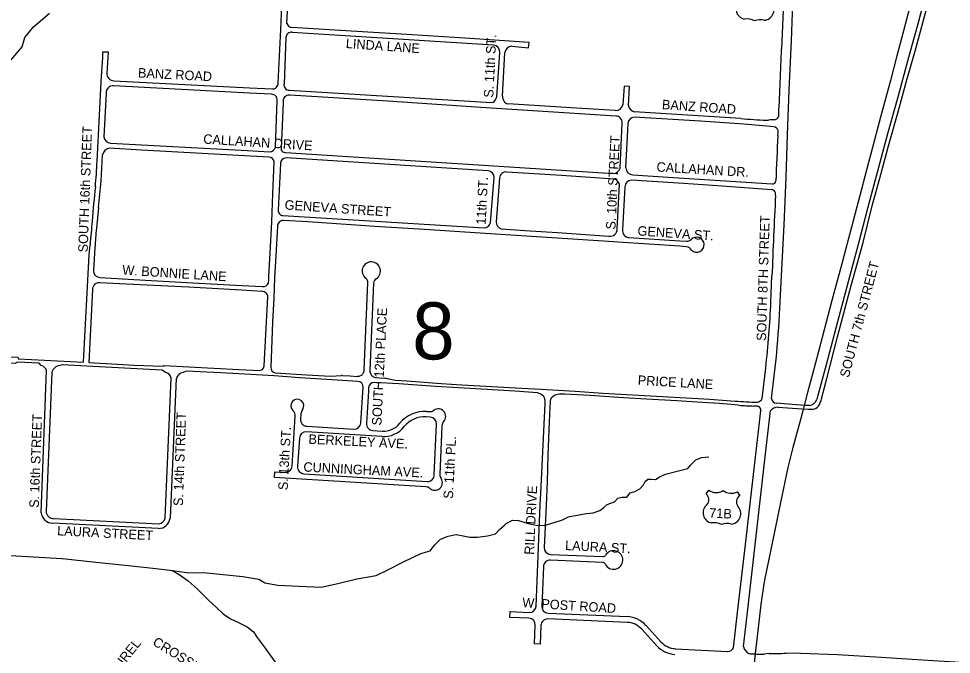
# Model space of a CAD drawing. Extents: x 0 to 712119, y 0 to 761125.
# Drawn here: x 681680 to 686589, y 720273 to 723620 of the extents above; entities that cross this region are included whole.
import ezdxf

# ---------------------------------------------------------------- set-up
doc = ezdxf.new("R2010")
doc.units = 0
for name, color, linetype in [('Arkansas-Missouri Railroad', 7, 'Continuous'), ('HWY signs', 7, 'Continuous'), ('PAVED ROADS', 7, 'Continuous'), ('Priority 8', 7, 'Continuous'), ('stream or creek', 7, 'Continuous'), ('street names', 7, 'Continuous')]:
    doc.layers.add(name, color=color, linetype=linetype)

msp = doc.modelspace()

# ---------------------------------------------------------------- linework, layer by layer
at = {"layer": 'Arkansas-Missouri Railroad'}
msp.add_lwpolyline([(686370.6, 723681.9), (686319.3, 723488.6), (686319.3, 723488.6), (686302.3, 723424.6), (686268, 723295.2), (686268, 723295.2), (686216.7, 723101.9), (686216.7, 723101.9), (686165.4, 722908.6), (686165.4, 722908.6), (686153.3, 722863.2), (686114.1, 722715.3), (686114.1, 722715.3), (686062.8, 722522), (686062.8, 722522), (686031.1, 722402.2), (686011.5, 722328.6), (686011.5, 722328.6), (685960.3, 722135.3), (685960.3, 722135.3), (685909, 721942), (685909, 721942), (685889.3, 721868), (685857.7, 721748.7), (685857.7, 721748.7), (685832, 721652), (685806.4, 721555.4), (685806.4, 721555.4), (685795.7, 721515), (685755.2, 721362), (685755.2, 721362), (685727.4, 721256.8), (685688, 721063.9), (685688, 721063.9), (685647.8, 720867.9), (685647.8, 720867.9), (685607.7, 720672), (685607.7, 720672), (685602, 720644.3), (685586.6, 720535.3), (685579.5, 720474.1), (685579.5, 720474.1), (685556.6, 720275.4), (685556.6, 720275.4), (685548.8, 720206.9)], dxfattribs=at)
at = {"layer": 'HWY signs'}
for points in [[(685297.6, 721119), (685312.7, 721137.4)], [(685387.6, 721135.4), (685387.6, 721135.4)], [(685462.3, 721129.6), (685475.4, 721109.7)]]:
    msp.add_lwpolyline(points, dxfattribs=at)
for centre, radius, start, end in [((685510.2, 723670.5), 54.5, 128.6765, 259.9158), ((685600.3, 723665.8), 54.5, 274.1051, 45.3444), ((685515, 723544.6), 73.6, 59.7374, 101.2498), ((685582.4, 723541.1), 73.6, 72.7711, 114.2835), ((685270.4, 721087.6), 41.5, 320.1078, 49.1208), ((685351.6, 721193.6), 68.4, 235.2382, 301.7199), ((685429.4, 721189.5), 68.4, 232.3011, 298.7827), ((685499.1, 721075.7), 41.5, 124.9002, 213.9131), ((685336.3, 721018.5), 54.5, 128.6765, 259.9158), ((685426.4, 721013.8), 54.5, 274.1051, 45.3444), ((685341.1, 720892.7), 73.6, 59.7374, 101.2498), ((685408.5, 720889.2), 73.6, 72.7711, 114.2835)]:
    msp.add_arc(centre, radius, start, end, dxfattribs=at)
at = {"layer": 'PAVED ROADS'}
for points in [[(685686.5, 722095.5), (685694.5, 722266), (685708.6, 722534.3), (685718.9, 722785.6), (685727, 723009), (685735.5, 723244), (685747.5, 723503.1), (685756.8, 723750.9), (685772.3, 724116.8), (685794.1, 724626.3), (685823.1, 725340.7)], [(685773.5, 725345.2), (685749.1, 724736.5), (685723.3, 724121.6), (685714.1, 723905.9), (685705.6, 723704.9), (685695.2, 723460.5)], [(686568.2, 724178.4), (686538.2, 724067.4), (686472.6, 723821.8), (686415.4, 723605.3), (686358.1, 723397), (686306.8, 723206.9), (686253.5, 723013.3), (686205.1, 722836.5), (686147.8, 722620.8), (686099, 722431.5), (686045, 722234.5), (685989, 722024.5), (685930.5, 721797.5), (685881.5, 721616)], [(685906.1, 721617.8), (685933.5, 721725), (685990, 721945), (686062.2, 722214.7), (686124.1, 722441.4), (686172.4, 722634.7), (686217.1, 722799.7), (686257.7, 722950.5), (686308.5, 723128.9), (686355, 723297.3), (686399.7, 723455.8), (686464.9, 723696.2), (686522.3, 723922), (686560.3, 724062.8), (686578.7, 724124.4)], [(683092, 723593.7), (683097.8, 723723.7), (683103.6, 723862.7)], [(683045, 723281.5), (683059.5, 723562.2), (683062.6, 723647.7), (683064.5, 723701.6), (683067.2, 723781)], [(684275.5, 723474.6), (684364, 723467.1), (684366.5, 723494.4), (684028.2, 723516.5), (683694.5, 723537.7), (683429.1, 723554.4), (683117.7, 723573.7)], [(683086.5, 723520), (683076.5, 723277)], [(684178.7, 723480.2), (683118.6, 723547.9)], [(682093, 722869), (682105.5, 723111), (682114.5, 723289), (682122.3, 723416.3), (682122.7, 723446), (682150.8, 723445.3), (682149.8, 723414), (682144.5, 723333)], [(684198.9, 723233.3), (684212, 723442.4)], [(684225.9, 723212.4), (684239.2, 723442.2)], [(682180.5, 723293.5), (682895, 723256), (683016.5, 723250)], [(682139.5, 723227.5), (682128.6, 722998.3)], [(683010, 723222), (682895.5, 723228.5), (682178.8, 723266.4)], [(683104, 723243.5), (684167.9, 723177.9)], [(684890, 723160.9), (684895, 723263.1), (684866, 723264.5), (684859.9, 723166.9)], [(683031, 722943), (683040.5, 723190.5)], [(683071.5, 723179), (683060.5, 722938.5)], [(684823, 723106.5), (684113, 723151.7), (683623, 723185), (683106.5, 723217)], [(684820.9, 723136), (684644.2, 723146.9), (684253.6, 723172.1)], [(685481.4, 723093.7), (685285, 723106.1), (684919.3, 723129.8)], [(685654.5, 723050), (685636.5, 723052), (685496, 723064), (685268.5, 723080), (684920, 723101)], [(685634.8, 723086.8), (685626.6, 723085.4)], [(685656.4, 723086.6), (685649.3, 723086.8)], [(684844.9, 722832.9), (684856.1, 723071.7), (684856.1, 723071.7)], [(684885.5, 723065.7), (684874.5, 722833.9)], [(682996, 722891.5), (682326.5, 722927), (682156, 722937.5)], [(682163.5, 722964.7), (682883.8, 722926.1), (683000.5, 722919)], [(683084.5, 722915), (684810, 722804.9)], [(684151, 722819), (683087.5, 722886.5)], [(682994.5, 722230), (682996, 722242.5), (682997, 722264), (683003, 722385.5), (683011.5, 722550), (683018, 722697.5), (683019, 722738.5), (683024.5, 722866.5)], [(683057, 722858), (683045.5, 722612.5)], [(684163.4, 722545.7), (684181.8, 722782.9)], [(684211, 722779.7), (684193.1, 722549.5)], [(684813.6, 722774.8), (684536.4, 722793.6), (684249.6, 722812.5)], [(684911.6, 722798.4), (685097.5, 722785), (685645.4, 722750.2)], [(684830.5, 722512.5), (684841.5, 722746)], [(684870.4, 722735), (684858, 722508)], [(685643, 722719.5), (685383, 722738.5), (685178.5, 722752), (684904.5, 722768.9)], [(682099.5, 722625.5), (682089, 722517)], [(683070.5, 722583.5), (684129.6, 722518)], [(685194.5, 722419.5), (685159.6, 722421.9), (684888.5, 722439.3), (684784.5, 722446.1), (684514.4, 722464.4), (684324.7, 722476.9), (684109.5, 722490.2), (683815.8, 722509.5), (683555, 722525.9), (683201, 722550), (683073, 722558)], [(683042, 722526.5), (683033.6, 722370.7), (683027, 722254), (683022.5, 722149.5), (683016.5, 722022), (683007, 721785)], [(684218.7, 722512.8), (684344.7, 722504.7), (684516.3, 722493.3), (684786.5, 722475)], [(684890.4, 722468.2), (685160, 722450.5), (685194.5, 722448)], [(682020.4, 721811), (682051, 722377), (682055.5, 722430)], [(682081, 722414.5), (682073, 722293.5)], [(682108, 722257), (682286.5, 722246.5), (682565.5, 722231.5), (682854.5, 722215.5), (682963, 722209.5)], [(685639, 722130), (685644.7, 722264)], [(682068.5, 722194.5), (682049, 721809.4)], [(682961.5, 722183), (682853, 722190), (682573, 722205.5), (682319, 722219), (682105, 722230)], [(683498.5, 721770.4), (683518, 722228.3)], [(683547.9, 722227), (683528.4, 721767.2)], [(682972, 721792), (682991, 722155.5)], [(681798.5, 721793.5), (681787.5, 721805.5), (681674, 721811.5), (681660.5, 721804.5), (681509.5, 721812), (681399.5, 721817.5), (681298, 721822), (680643, 721852.5), (680562.5, 721856.5), (680505.5, 721857.5), (680412, 721859.5)], [(681486, 721846), (681675, 721837.5), (681679.5, 721829), (682020.4, 721811)], [(682049, 721809.4), (682287.5, 721796.5), (682438, 721790), (682443, 721793.5), (682839.2, 721773.7), (682949, 721768)], [(685643, 721619.5), (685666.5, 721826.5)], [(681797.5, 721019), (681826.5, 721767)], [(681854, 721756.5), (681824, 721026)], [(681909, 721797.5), (681896.5, 721794.5)], [(682452, 721757.5), (682435.5, 721769.5), (682069.5, 721789.5), (681909, 721797.5)], [(683464.2, 721710.4), (683464.2, 721710.6), (683330.4, 721719), (683157.7, 721729.8), (683024.5, 721739), (682744.5, 721755), (682560.5, 721764.5), (682545, 721757)], [(683030.5, 721756), (683196.5, 721745.5), (683320.5, 721737.5), (683378.1, 721741.4)], [(683492.8, 721751.7), (683492.4, 721751.9)], [(685593.5, 721621), (685612, 721782)], [(682450, 720992), (682481.5, 721727.5)], [(682509.5, 721725), (682477, 720990)], [(683384.1, 721741.9), (683425.1, 721739.2), (683461.4, 721736.9)], [(683480.6, 721741.3), (683480.8, 721740.8)], [(683532.9, 721748.5), (683532.5, 721748.3)], [(683543.4, 721736.4), (683543.7, 721736.8)], [(684402.8, 720527.3), (684425.4, 721059.8), (684428, 721120.1), (684450, 721593.5), (684451, 721604), (684451, 721611), (684449, 721617.5), (684446.5, 721623.5), (684443, 721630), (684435.5, 721638), (684424, 721645.5), (684410.5, 721650.5), (684290.4, 721658.7), (684115.3, 721669.8), (683873.4, 721683.8), (683681.5, 721697.5), (683552.1, 721705.3)], [(683561.2, 721730.7), (683580.9, 721729.5), (683606.8, 721728.1)], [(683611.3, 721727.4), (683661.5, 721716), (683661.5, 721716)], [(683661.5, 721716), (683723.5, 721712.5), (683904, 721700), (684011.5, 721693), (684138, 721685), (684294, 721676.5), (684430, 721668.5), (684608.5, 721659), (684754.5, 721649), (685068.5, 721630.5), (685317, 721617), (685451, 721607)], [(683481.1, 721491.7), (683492.7, 721678)], [(683521.7, 721676.7), (683520.6, 721658.7), (683510, 721489.9)], [(685469, 721584.5), (685368.5, 721593.5), (685276.4, 721599.5), (685143.6, 721608.1), (684983.9, 721617), (684863.7, 721624.4), (684688.6, 721635.6), (684554, 721642.5), (684526, 721643), (684515, 721641), (684504, 721637), (684495, 721632.5), (684488, 721628), (684483, 721622.5), (684479.5, 721616.5), (684477.5, 721610.5), (684476.5, 721605), (684472, 721500), (684464.5, 721321.5), (684460.6, 721181.9), (684455.4, 721058), (684445.9, 720835.7)], [(685442.3, 720307.9), (685464, 720494), (685508.5, 720881.5), (685552.6, 721265.5), (685579.2, 721493.8), (685586, 721557.5)], [(685495.5, 720314.5), (685519.5, 720526), (685604, 721267), (685636.5, 721556)], [(685566.5, 721580), (685550, 721580.5)], [(685584, 721568), (685580, 721573.5)], [(685841.5, 721583.5), (685821, 721583), (685750.5, 721589.5), (685667.5, 721595)], [(685677, 721575), (685801.5, 721565.5), (685836, 721563.5), (685862, 721564.5)], [(683118.8, 721263.9), (683135.4, 721527.5)], [(683165.2, 721539.9), (683163.4, 721511.6)], [(683845.7, 721521.9), (683824.7, 721523.3)], [(683826.7, 721552.2), (683841.2, 721551.3)], [(683196.6, 721473.9), (683443.4, 721458.5)], [(683867.4, 721217.7), (683878.8, 721484.9)], [(683907.4, 721476.6), (683896.5, 721220.6)], [(683157.2, 721411.8), (683147.8, 721262.1)], [(683591.6, 721420.1), (683194.8, 721445)], [(683543.2, 721452.2), (683593.4, 721449.1)], [(683823.5, 721155.1), (683026.7, 721205), (683028.5, 721234), (683081.2, 721230.7)], [(683181, 721224.4), (683829.7, 721183.8)], [(682415.5, 720935.5), (681859.5, 720963.5)], [(681865, 720989), (682417.5, 720961)], [(684751.9, 720757.6), (684478.1, 720769.3)], [(684479.4, 720799.3), (684753.2, 720787.6)], [(684441.7, 720735.8), (684432.7, 720526)], [(684265.7, 720468), (684267.1, 720498), (684366.3, 720493.8)], [(684466.2, 720489.5), (684883.4, 720471.8)], [(684365, 720463.8), (684265.7, 720468)], [(684428.5, 720426.1), (684424.2, 720326.3), (684394.3, 720327.9), (684398.5, 720427.4)], [(684882.1, 720441.8), (684464.9, 720459.6)], [(684981.1, 720426.1), (685060.1, 720339.1)], [(685037.9, 720318.9), (684958.9, 720405.9)], [(685135.6, 720303.2), (685411.5, 720288.5)], [(685630.5, 720278.5), (685604, 720274.5)], [(688147.5, 720143.5), (688112.5, 720143.5), (687799.5, 720160), (687514.5, 720180), (687351.5, 720185.5), (687076.5, 720202.7), (686756.3, 720223), (686492, 720240), (686219.5, 720257.5), (685990, 720270), (685795, 720277.5), (685717.5, 720279)]]:
    msp.add_lwpolyline(points, dxfattribs=at)
for centre, radius, start, end in [((683118.4, 723601.1), 27.5, 195.6597, 268.5413), ((683113.8, 723521), 27.4, 79.9384, 182.096), ((684176.1, 723444.4), 36, 356.9071, 85.807), ((684275.3, 723438.4), 36.3, 89.6802, 173.8729), ((660717.5, 724361.9), 24994, 357.14841, 357.93307), ((682180.2, 723329.4), 35.9, 174.2913, 270.4004), ((683016.1, 723279), 29, 270.8406, 4.8842), ((683103.5, 723271.1), 27.6, 167.6781, 271.0867), ((682177, 723228.9), 37.5, 87.3168, 182.188), ((683010.6, 723192.1), 29.9, 356.9417, 91.2102), ((684064.3, 723238.5), 134.7, 343.978, 357.7926), ((683103.6, 723184.6), 32.6, 84.8571, 189.8495), ((684163.9, 723208.4), 30.7, 277.5289, 346.7301), ((684301, 723219.1), 75.3, 185.0919, 205.611), ((684256.2, 723197.6), 25.6, 205.5363, 264.2188), ((684823.2, 723173.2), 37.2, 266.4761, 350.1768), ((684929.2, 723168.4), 39.9, 190.8858, 255.6086), ((684823.7, 723074.1), 32.5, 355.8132, 91.2539), ((684922.1, 723064.4), 36.6, 93.2452, 177.9279), ((686520.9, 738132.6), 15074.8, 266.04593, 266.5571), ((685619.8, 723121), 36.2, 263.362, 280.746), ((685642.4, 722998.1), 89, 85.597, 94.9004), ((685653, 723115.6), 29.2, 276.718, 337.7399), ((685341.8, 723123.6), 338.7, 356.7696, 359.1396), ((685652, 723024.9), 25.3, 14.0707, 84.2991), ((685332, 723025), 344.6, 356.7556, 0.9978), ((682164.6, 723000.9), 36.1, 184.0923, 268.2189), ((694616.1, 722492.4), 8954.8, 176.71541, 178.24293), ((682165.9, 722891.8), 46.8, 102.2503, 166.1128), ((683000.5, 722950.4), 31.4, 269.9989, 346.3984), ((683082.7, 722937.1), 22.2, 176.4888, 274.7173), ((679642.5, 722951), 2478.5, 352.454, 358.8907), ((682996.4, 722863.3), 28.2, 6.5859, 90.9001), ((683086.8, 722856.7), 29.8, 88.6171, 177.4999), ((674154.2, 723356.1), 7953.7, 355.52183, 356.4887), ((684808.8, 722842.2), 37.3, 271.9114, 345.6212), ((684912.4, 722836.3), 37.9, 183.7313, 268.8777), ((684147.6, 722784.9), 34.2, 356.6424, 84.3139), ((684244.6, 722779.3), 33.6, 81.4096, 179.1956), ((686685, 722215.2), 4630.7, 173.5534, 175.8004), ((684807.5, 722740.9), 34.4, 8.5512, 79.8154), ((684905.9, 722733.4), 35.5, 92.2603, 177.3893), ((685647.3, 722768.3), 18.2, 263.7168, 355.8154), ((685643.3, 722699.3), 20.2, 12.0004, 90.7454), ((708762.5, 721455.3), 23132, 176.94371, 177.99658), ((685609.8, 722694.5), 54, 353.7655, 9.6108), ((683071.8, 722609.9), 26.5, 174.4314, 267.0958), ((686753.6, 722065.4), 4712.2, 174.0453, 175.5629), ((683072.6, 722527.4), 30.6, 89.183, 181.7337), ((684127, 722555.6), 37.7, 273.8232, 344.736), ((684231.4, 722549), 38.3, 179.235, 250.6335), ((684043.5, 722312.9), 1965.1, 174.0382, 177.0362), ((684792.2, 722512.9), 38.3, 261.3946, 359.4458), ((684892.9, 722503.4), 35.2, 172.4237, 265.8668), ((685196.2, 722482.7), 34.8, 267.117, 309.7529), ((685248.3, 722430.3), 39.4, 227.0519, 139.2496), ((685190.5, 722384.2), 35.5, 29.1114, 83.5085), ((683535.6, 722291.3), 48, 302.8061, 232.346), ((682108.9, 722292.8), 35.9, 178.9606, 268.6357), ((683488, 722229.5), 30, 357.576, 52.3347), ((683577.9, 722225.7), 30, 122.8174, 177.5758), ((682103.5, 722195), 35, 87.6219, 180.7866), ((682967.4, 722237.3), 28.1, 261.0697, 345.0419), ((682962.8, 722154.9), 28.2, 1.318, 92.7011), ((680036.7, 722389.6), 5608.3, 353.7803, 357.3468), ((679875.3, 722392.3), 5818.7, 354.41975, 357.07608), ((681787, 721753.4), 41.8, 19.0805, 74.0726), ((681902.7, 721744.8), 50.1, 97.1292, 166.4717), ((682448, 721724), 33.7, 5.9025, 83.1346), ((682549.8, 721716), 41.2, 96.6237, 167.4398), ((682947.3, 721792.7), 24.7, 273.9731, 358.4646), ((683033.5, 721782.5), 26.7, 174.5738, 263.465), ((683463.6, 721771.9), 35.5, 299.0273, 325.3256), ((683463.6, 721771.9), 35, 325.3256, 357.5712), ((683563.4, 721765.7), 35, 177.5713, 209.4074), ((683382.8, 721721.4), 20.5, 86.4547, 103.3819), ((683463.6, 721771.9), 35, 266.4547, 299.0273), ((683462.3, 721680), 30.5, 356.415, 86.415), ((683552.1, 721674.8), 30.5, 90.0559, 176.415), ((683563.4, 721765.7), 35.5, 209.4074, 235.6635), ((683563.4, 721765.7), 35, 235.6635, 266.4717), ((683605.6, 721707.7), 20.5, 73.877, 86.4702), ((683146.4, 721582), 34.5, 320.7403, 228.3736), ((685626, 723695.6), 2095.9, 265.2115, 268.4016), ((685563, 721633), 32.8, 277.9466, 338.5622), ((685668.6, 721620.6), 25.7, 182.5559, 267.4441), ((685833.1, 721634.7), 51.9, 279.334, 338.8538), ((685735.9, 721671.2), 178.4, 329.4729, 342.5802), ((683099.9, 721529.7), 35.5, 356.415, 48.3736), ((683200.6, 721537.7), 35.5, 140.7403, 176.415), ((683815.5, 721388.1), 164.5, 86.0901, 141.494), ((683843.6, 721586.7), 35.5, 266.0901, 306.4363), ((683888.2, 721526.3), 39.5, 316.8693, 126.4363), ((685588.2, 723175.5), 1595.4, 265.7165, 268.6293), ((685557.9, 721544.9), 36.2, 52.3364, 76.2437), ((685562.6, 721558.5), 23.5, 357.6214, 23.9472), ((685679, 721518), 57.1, 92.0503, 138.2156), ((685857.5, 721603.8), 39.6, 276.4645, 323.9896), ((683198.8, 721509.3), 35.5, 176.415, 266.415), ((683815.5, 721388.1), 135.5, 86.0901, 141.494), ((683843.3, 721486.5), 35.5, 357.5565, 86.0901), ((683445.6, 721493.9), 35.5, 266.415, 356.415), ((683545.4, 721487.6), 35.5, 176.415, 266.415), ((683600.3, 721559.3), 139.5, 266.415, 321.494), ((683600.3, 721559.3), 110.5, 266.4151, 321.4939), ((683942.9, 721475.1), 35.5, 136.8693, 177.5575), ((683192.6, 721409.5), 35.5, 86.415, 176.415), ((683083.4, 721266.1), 35.5, 266.415, 356.415), ((683183.2, 721259.8), 35.5, 176.415, 266.415), ((683831.9, 721219.2), 35.5, 266.415, 357.5565), ((683932, 721219.1), 35.5, 177.5575, 214.5633), ((683870.2, 721176.5), 39.5, 229.2947, 34.5633), ((683821.3, 721119.7), 35.5, 49.2947, 86.415), ((681860.8, 721027.3), 63.8, 187.4814, 268.8513), ((681861.1, 721025.9), 37.1, 179.7688, 276.1026), ((682414.3, 720998.8), 63.3, 271.0735, 352.0199), ((682414.7, 720996.5), 35.6, 274.4973, 352.7963), ((684480.9, 720834.2), 35, 177.5653, 267.5653), ((684810.8, 720770.1), 49, 207.0728, 148.0578), ((684476.6, 720734.3), 35, 87.5653, 177.5653), ((684754, 720805.6), 18, 267.5653, 328.0578), ((684751.2, 720739.7), 18, 27.0728, 87.5653), ((684367.8, 720528.8), 35, 267.5653, 357.5653), ((684467.7, 720524.5), 35, 177.5653, 267.565), ((684363.6, 720428.8), 35, 357.5653, 87.5653), ((684463.5, 720424.6), 35, 87.5653, 177.5653), ((684877.5, 720331.9), 110, 42.2543, 87.5653), ((684877.5, 720331.9), 140, 42.2543, 87.5653), ((685141.5, 720413.1), 110, 222.2543, 266.94), ((685141.5, 720413.1), 140, 222.2543, 266.94), ((685410.7, 720324), 35.5, 271.2949, 333.0398), ((685548.2, 720323.6), 53.5, 189.8189, 240.6763), ((685608.3, 721760), 1485.6, 266.6715, 269.836), ((685657.9, 723087.4), 2809.1, 269.442, 271.2166)]:
    msp.add_arc(centre, radius, start, end, dxfattribs=at)
at = {"layer": 'stream or creek'}
for points in [[(681641, 723403.3), (681697.3, 723472.1), (681711.3, 723520.5), (681758.2, 723576.7), (681842.6, 723648.7)], [(681633.5, 720793.4), (681758.5, 720787.2), (681907.1, 720778), (681910.1, 720777.8), (682086.6, 720759), (682257, 720740.3), (682417.9, 720723.2), (682489.2, 720714.2), (682575.7, 720702.8), (682652.3, 720704.4), (682755.4, 720693.4), (682860.1, 720682.5), (682942.9, 720668.4), (682964, 720656.4), (682975.7, 720649.7), (683042.9, 720637.2), (683155.4, 720632.5), (683271, 720626.3), (683360.1, 720646.6), (683460.1, 720670), (683561.6, 720688.8), (683619.5, 720716.9), (683705.4, 720760.6), (683796, 720804.4), (683846, 720818.4), (683869.5, 720849.7), (683888.9, 720869.1), (683899.1, 720879.4), (683939.8, 720895), (683971.3, 720902), (683982, 720904.4), (684019.5, 720898.1), (684053.9, 720890), (684093.9, 720890), (684146.9, 720897.1), (684189.9, 720908), (684210.9, 720930), (684234.2, 720951.4), (684245.9, 720962), (684278.9, 720980), (684310.9, 720978.1), (684345, 720966.9), (684353.9, 720964.1), (684403.9, 720953), (684445.9, 720952.1), (684497.9, 720967.1), (684541.9, 720982), (684570.8, 720995.3), (684578.9, 720999.1), (684590.8, 721001.1), (684619.9, 721006), (684667.9, 721014), (684703.9, 721018), (684737.9, 721030), (684758.9, 721047.1), (684776.9, 721062), (684815.9, 721077), (684816.8, 721078), (684833.9, 721096), (684856.9, 721100.1), (684879.9, 721101), (684898.9, 721123), (684922, 721131.1), (684949.9, 721144), (684968.9, 721166.1), (684976.9, 721184), (684990.9, 721196), (685005.8, 721195.2), (685008.9, 721195), (685030.9, 721194), (685055.9, 721209.1), (685084, 721221), (685137.9, 721235.1), (685173.9, 721244), (685201.9, 721251.1), (685215.9, 721269), (685243.9, 721298), (685274, 721310.1), (685311.9, 721314)], [(682489.2, 720714.2), (682529.8, 720690.7), (682572, 720661), (682618.9, 720618.9), (682679.8, 720556.4), (682721.7, 720519.8), (682756.7, 720486.8), (682794.7, 720460.7), (682836.7, 720440.8), (682881.7, 720418.7), (682915.7, 720391.7), (682935.7, 720361.8), (682971.7, 720312.8), (683029.7, 720232.8)]]:
    msp.add_lwpolyline(points, dxfattribs=at)

# ---------------------------------------------------------------- texts
at = {"layer": 'HWY signs'}
msp.add_text('71B', height=50, rotation=357.0105, dxfattribs=at).set_placement((685313.2, 720993.5))
at = {"layer": 'Priority 8'}
msp.add_text('8', height=300, dxfattribs=at).set_placement((683751.1, 721826.1))
at = {"layer": 'street names'}
for s, rotation, p in [('S. 11th ST.', 87.193, (684177.5, 723202.7)), ('LINDA LANE', 355.9538, (683400.3, 723465.6)), ('BANZ ROAD', 356.9997, (682306.6, 723310.6)), ('BANZ ROAD', 356.2241, (685064.4, 723143.7)), ('SOUTH 16th STREET', 87.9877, (682042.6, 722388.7)), ('CALLAHAN DRIVE', 356.4365, (682650, 722962.4)), ('S. 10th STREET', 87.193, (684820.5, 722508.8)), ('CALLAHAN DR.', 356.6214, (685035.8, 722815.3)), ('11th ST.', 87.193, (684137.5, 722534.3)), ('GENEVA STREET', 356.1015, (683078.4, 722615.7)), ('SOUTH 8TH STREET', 88.2731, (685613.2, 721922.7)), ('GENEVA ST.', 356.1015, (684935.8, 722479)), ('SOUTH 7th STREET', 75.2264, (686049, 721726.9)), ('W. BONNIE LANE', 356.2916, (682223.8, 722272.8)), ('SOUTH 12th PLACE', 87.193, (683588.6, 721477.1)), ('PRICE LANE', 356.6463, (684937.2, 721692.6)), ('S. 16th STREET', 87.9877, (681785.3, 721043.5)), ('S. 14th STREET', 87.9877, (682543.8, 721053.5)), ('S. 13th ST.', 86.9838, (683095.2, 721136.6)), ('BERKELEY AVE.', 357.1455, (683204, 721382.3)), ('S. 11th PL.', 86.9838, (683965.1, 721091)), ('CUNNINGHAM AVE.', 357.1455, (683177.5, 721235.8)), ('RILL DRIVE', 87.193, (684391.3, 720796.5)), ('LAURA STREET', 357.031, (681881.4, 720900.2)), ('LAURA ST.', 357.031, (684554.7, 720822.8)), ('W. POST ROAD', 356.3799, (684329.3, 720521.6)), ('LAUREL', 51.3709, (682164.4, 720126.7)), ('CROSSING', 328.3481, (682380.7, 720325.6))]:
    msp.add_text(s, height=50, rotation=rotation, dxfattribs=at).set_placement(p)

doc.saveas('drawing.dxf')
